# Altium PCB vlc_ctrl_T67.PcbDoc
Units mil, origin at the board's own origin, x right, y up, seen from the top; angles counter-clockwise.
Board outline 1000 x 850 mil, 2 copper layers (Top Layer, Bottom Layer); 16 components, 12 nets, 46 pads, 1 vias.
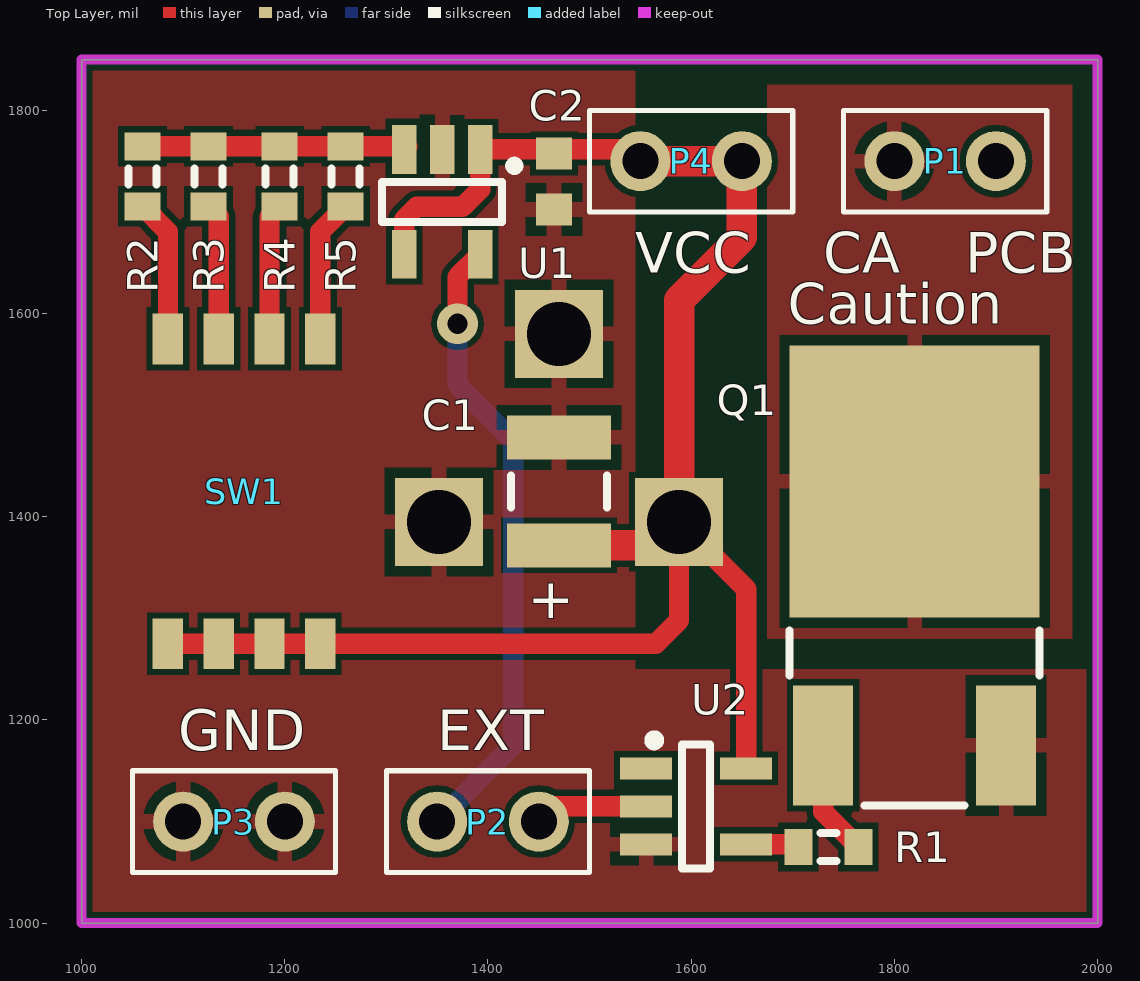
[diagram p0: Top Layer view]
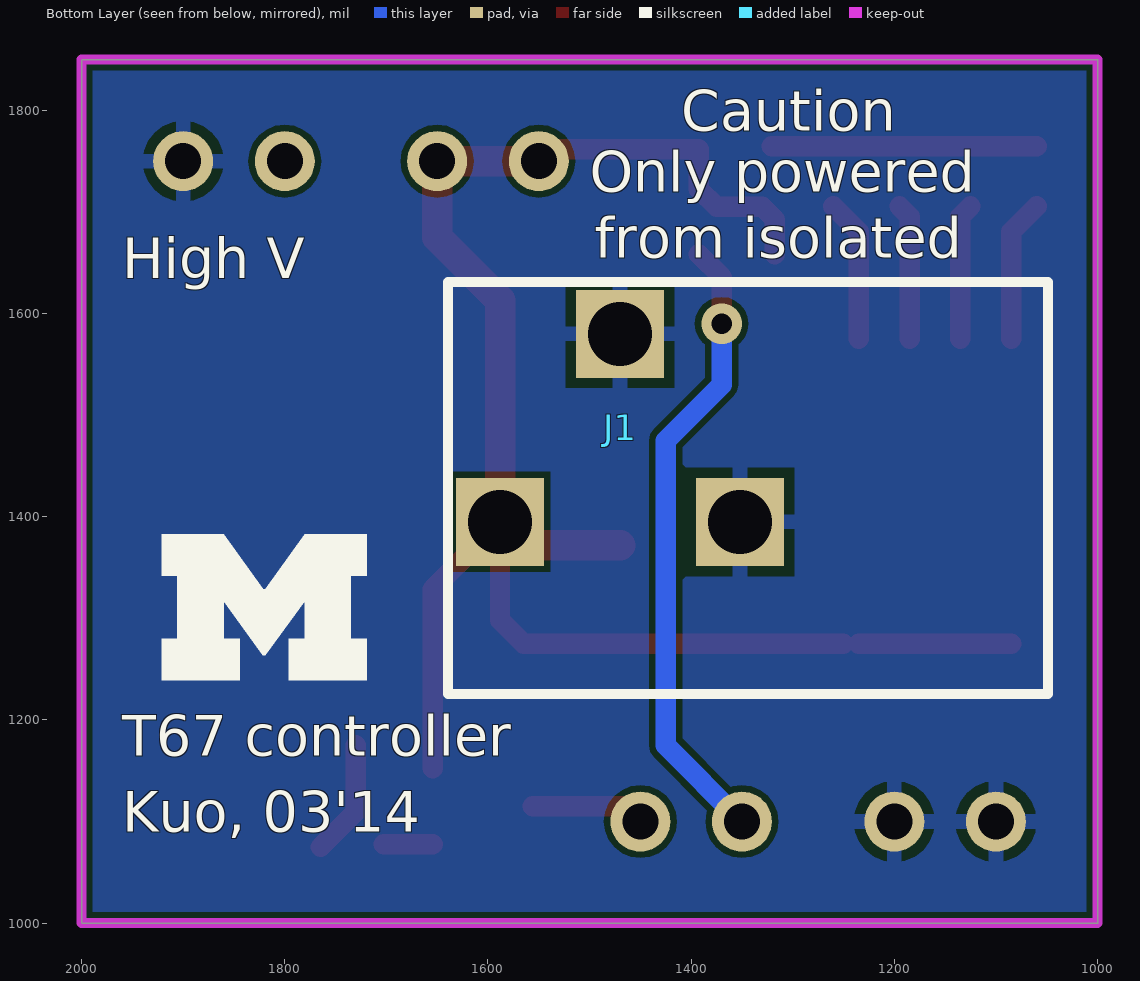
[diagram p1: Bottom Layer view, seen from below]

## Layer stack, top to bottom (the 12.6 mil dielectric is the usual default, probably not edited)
Top Solder: solder mask 0.4, Solder Resist, Dk 3.5
Top Layer: signal copper 1.4
Dielectric 1: dielectric 12.6, FR-4, Dk 4.8
Bottom Layer: signal copper 1.4
Bottom Solder: solder mask 0.4, Solder Resist, Dk 3.5

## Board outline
1000,1000 1000,1850 2000,1850 2000,1000

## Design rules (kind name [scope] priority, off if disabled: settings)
Clearance "Clearance~Sunstone Circuits" [All] p1: gap=6 // Sunstone Circuits Minimum Clearance Rule (Double Sided)
HoleSize "HoleSize~Sunstone Circuits" [All] p1: absolutevalues=TRUE maxlimit=251 minlimit=16 maxpercent=80.000 minpercent=20.000 // SSC Hole Size Rule For Single Sided & Double Sided Designs.
HoleSize Testpoint [All] p2: absolutevalues=TRUE maxlimit=100 minlimit=1 maxpercent=80.000 minpercent=20.000
HoleSize TestPointUsage [All] p3: absolutevalues=TRUE maxlimit=100 minlimit=1 maxpercent=80.000 minpercent=20.000
MinimumAnnularRing "MinimumAnnularRing~Sunstone Circuits" [All] p1: minimumring=7 // Sunstone Circuits Minimum Annular Ring (Double Sided)
PlaneClearance "PlaneClearance~Sunstone Circuits" [All] p1: clearance=12 // Sunstone Circuits Power Plane Clearance Rule (Double Sided)
PlaneConnect "PlaneConnect~Sunstone Circuits" [All] p1: planeconnectstyle=Relief reliefexpansion=10 reliefentries=4 reliefconductorwidth=8 reliefairgap=10 // Sunstone Circuits Power Plane Connect Rule (Double Sided)
PolygonConnect "PolygonConnect~Sunstone Circuits" [All] p1: connectstyle=Relief reliefconductorwidth=15 reliefentries=4 polygonreliefangle="90 Angle" airgapwidth=10 // Sunstone Circuits Polygon Connect Style (Double Sided)
RoomDefinition vlc_ctrl_T67 [InComponentClass('vlc_ctrl_T67')] p1: confinementstyle=ConfineIn formatcopy=TRUE lockcomponents=FALSE outline 1026.38,1675.79 1026.38,1794.21 1282.01,1794.21 1282.01,1798.59 1487.5,1798.59 1487.5,1812.5 1962.5,1812.5 1962.5,1687.5 1959.92,1687.5 1959.92,1102.01 1848.62,1102.01 1848.62,1045.79 1695.71,1045.79 1695.71,1038.07 1512.5,1038.07 1512.5,1037.5 1037.5,1037.5 1037.5,1210.71 1031.35,1210.71 1031.35,1675.79
RoutingVias "RoutingVias~Sunstone Circuits" [All] p1: holewidth=16 width=30 viastyle="Through Hole" minholewidth=16 minwidth=30 maxholewidth=20 maxwidth=40 // Sunstone Circuits Routing Vias Rule (Double Sided)
ShortCircuit "ShortCircuit~Sunstone Circuits" [All] p1: allowed=FALSE // Sunstone Circuits Short Circuit Rule~Do Not Allow (Double Sided)
SolderMaskExpansion "SolderMaskExpansion~Sunstone Circuits" [All] p1: expansion=3 // Sunstone Circuits Solder Mask Expansion Rule (Double Sided)
ViasUnderSMD "ViasUnderSMD~Sunstone Circuits" [All] p1: allowed=FALSE // Sunstone Circuits Vias Under SMD~Do Not Allow (Double Sided)
Width "Width~Sunstone Circuits" [All] p1: maxlimit=100 minlimit=6 preferedwidth=10 // Sunstone Circuits Minimum Width Rule (Double Sided)
25 further rules are at their usual default settings.

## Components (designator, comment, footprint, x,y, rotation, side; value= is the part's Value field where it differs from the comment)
C1 "Cap Semi" C1210 1470,1425 r270 top
C2 "Cap Semi" 1608[0603] 1465,1730 r90 top
J1 "PJ-102AH" PJ-102AH 1470,1395 r270 bottom
P1 "1 x 2 header" "1X2 HEADER" 1850,1750 r0 top
P2 "1 x 2 header" "1X2 HEADER" 1400,1100 r0 top
P3 "1 x 2 header" "1X2 HEADER" 1150,1100 r180 top
P4 "1 x 2 header" "1X2 HEADER" 1600,1750 r180 top
Q1 "AOD3N60" TO252 1820,1175 r0 top
R1 "Res3" J1-0603 1735,1075 r180 top
R2 "Res3" J1-0603 1060,1735 r270 top
R3 "Res3" J1-0603 1125,1735 r270 top
R4 "Res3" J1-0603 1195,1735 r270 top
R5 "Res3" J1-0603 1260,1735 r270 top
SW1 "CHS-04TB" CHS04TB 1160,1425 r0 top
U1 "LTC6900" TSOT23 1355,1710 r180 top
U2 "SN74LVC1G17" SOT23-5 1605,1115 r0 top

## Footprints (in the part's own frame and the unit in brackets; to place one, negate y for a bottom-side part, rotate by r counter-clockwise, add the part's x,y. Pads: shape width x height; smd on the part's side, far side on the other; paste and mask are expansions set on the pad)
"1X2 HEADER" [mm] "1x2 header, 100 mils"
  round 1.5 hole 0.9: 1(-1.27,0) 2(1.27,0)
  silkscreen extent -2.54,-1.27 2.54,1.27, body extent -2.53,-1.26 2.53,1.26, height 8.38
1608[0603] [mm] "Chip Capacitor, Body 1.6x0.8mm, IPC High Density"
  rect 0.8x0.9 smd: 1(-0.7,0) 2(0.7,0)
  body extent -0.87,-0.48 0.87,0.48, height 1.3
C1210 [mm] "Chip Capacitor, Body 3.2x2.5mm, IPC High Density"
  rect 1.1x2.6 smd: 1(-1.35,0) 2(1.35,0)
  silkscreen extent -0.4,-1.2 0.4,1.2, body extent -1.7,-1.35 1.7,1.35, height 1.3
CHS04TB [mm] "4 POS DIP SWITCH"
  rect 0.76x1.27 smd: 1(-1.905,-3.81) 2(-1.905,3.81) 3(-0.635,-3.81) 4(-0.635,3.81) 5(0.635,-3.81) 6(0.635,3.81) 7(1.905,-3.81) 8(1.905,3.81)
J1-0603 [mm] "Chip Resistor, Body 1.6x0.8mm, IPC High Density"
  rect 0.7x0.9 smd: 1(-0.75,0) 2(0.75,0)
  silkscreen extent -0.2,-0.35 0.2,0.35, body extent -0.85,-0.48 0.85,0.48, height 0.9
PJ-102AH [mm] "Power Jack"
  rect 2.2x2.2 hole 1.6: 1(0,-3) 2(0,3) 3(-4.7,0)
  silkscreen extent -6,-4.3 4.3,10.7, body extent -5.75,-3.99 4.08,10.89, height 10
SOT23-5 [mm] "SOT23, 5-Leads, Body 2.9x1.6mm, Pitch 0.95mm, Lead Span 2.8mm, IPC High Density"
  rect 1.3x0.55 smd: 1(-1.25,0.95) 2(-1.25,0) 3(-1.25,-0.95) 4(1.25,-0.95) 5(1.25,0.95)
  silkscreen extent -1.17,-1.55 0.35,1.77, body extent -0.67,-1.5 0.65,1.5, height 1.45
TO252 [mm] "TO252-3"
  rect 1.5x3 smd: 1(-2.286,0) 3(2.286,0)
  rect 6.25x6.8 smd: 4(0,6.6)
  silkscreen extent -3.13,-1.5 3.13,2.88, body extent -3.3,2.98 3.3,9.08, height 2.3
TSOT23 [mm]
  rect 0.62x1.22 smd: 1(-0.95,-1.31) 2(0,-1.31) 3(0.95,-1.31) 4(0.95,1.31) 5(-0.95,1.31)
  silkscreen extent -1.9,-1 1.5,0.5

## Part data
C1 C2: "Capacitor (Semiconductor SIM Model)"
J1: "CONN PWR JACK 2.1X5.5MM HIGH CUR"
P1 P2 P3 P4: "100 mils standard header"
Q1: "600V,2.5A N-Channel MOSFET"
R1 R2 R3 R4 R5: "Resistor"
SW1: "SLIDE SWITCHES"
U1: "Low Power, 1kHz to 20MHz   Resistor Set SOT-23 Oscillator"
U2: "SINGLE SCHMITT-TRIGGER BUFFER"

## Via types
v1: diameter 40, hole 20, Top Layer to Bottom Layer, 1 vias

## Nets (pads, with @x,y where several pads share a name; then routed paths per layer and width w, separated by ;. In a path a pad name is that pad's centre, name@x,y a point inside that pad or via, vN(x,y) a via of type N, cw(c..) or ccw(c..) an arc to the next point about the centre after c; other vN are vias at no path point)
GND: C1.1 C2.1 J1.2 J1.3 P1.2 P3.1 P3.2 Q1.3 U1.2 U2.3
NetP1_1: P1.1 Q1.4
NetP2_1: P2.1 U1.5 | length 621.6
  Top Layer w20: v1(1370,1590) 1370,1636.02 U1.5
  Bottom Layer w20: P2.1 1425,1175 1425,1475 1370,1530 v1(1370,1590)
NetP2_2: P2.2 U2.2 | length 112
  Top Layer w20: P2.2 1465,1115 U2.2
NetQ1_1: Q1.1 R1.1 | length 114.3
  Top Layer w20: Q1.1 1730,1109.53 R1.1
NetR1_2: R1.2 U2.4 | length 48.7
  Top Layer w20: U2.4 R1.2@1702.87,1077.6
NetR2_1: R2.1 R3.1 R4.1 R5.1 U1.3 | length 260.6
  Top Layer w20: R2.1 R3.1 R4.1 R5.1 U1.3@1320.55,1764.53
NetR2_2: R2.2 SW1.2 | length 140.8
  Top Layer w20: R2.2 1085,1680.47 SW1.2
NetR3_2: R3.2 SW1.4 | length 134.6
  Top Layer w20: R3.2 1135,1695.47 SW1.4
NetR4_2: R4.2 SW1.6 | length 134.6
  Top Layer w20: SW1.6 1185,1695.47 R4.2
NetR5_2: R5.2 SW1.8 | length 140.8
  Top Layer w20: SW1.8 1235,1680.47 R5.2
VCC5: C1.2 C2.2 J1.1 P4.1 P4.2 SW1.1 SW1.3 SW1.5 SW1.7 U1.1 U1.4 U2.5 | length 1795.8
  Top Layer w20: SW1.1 SW1.3 SW1.5 SW1.7 ; 1250,1275 1565,1275 1588.11,1298.11 J1.1 1654.21,1328.9 U2.5 ; U1.4 1317.6,1692.6 1330,1705 1375,1705 1392.4,1722.4 U1.1 1538.43,1761.57 P4.2
  Top Layer w30: C1.2 1564.96,1371.85 J1.1 1588.11,1613.11 1650,1675 P4.1 P4.2
pads on no net: U2.1

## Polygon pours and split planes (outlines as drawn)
GND on Bottom Layer "Bottom Layer-No Net" (solid, pour order 8): 1000,1000 2000,1000 2000,1850 1000,1850
GND on Top Layer "Bottom Layer-No Net" (solid, pour order 6): 2000,1250 2000,1000 1000,1000 1000,1850 1545,1850 1545,1250
NetP1_1 on Top Layer "Bottom Layer-No Net" (solid, pour order 2): 1675,1280 1975,1280 1975,1825 1675,1825

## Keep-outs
Keep-Out Layer:
  the board outline again, w10

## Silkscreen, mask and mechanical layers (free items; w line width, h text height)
Top Overlay:
  text "VCC" at 1545,1640 h40
  text "CA" at 1730,1640 h40
  text "PCB" at 1870,1640 h40
  text "Caution" at 1695,1590 h40
  text "+" at 1485,1300 h40
  text "GND" at 1095,1170 h40
  text "EXT" at 1350,1170 h40
Bottom Overlay:
  region: 1920.96,1239.04 1844.23,1239.04 1844.23,1280 1859.84,1280 1859.84,1317.06 1821.8,1263.74 1819.2,1263.74 1780.51,1317.06 1780.51,1280 1796.12,1280 1796.12,1239.04 1719.4,1239.04 1719.4,1280 1735,1280 1735,1341.77 1719.4,1341.77 1719.4,1382.73 1780.19,1382.73 1819.2,1328.76 1821.15,1328.76 1860.16,1382.73 1920.96,1382.73 1920.96,1341.77 1906,1341.77 1906,1280 1920.96,1280
  text "Caution" at 1410,1780 h40
  text "Only powered" at 1500,1720 h40
  text "from isolated" at 1495,1655 h40
  text "High V" at 1960,1635 h40
  text "T67 controller" at 1960,1165 h40
  text "Kuo, 03'14" at 1960,1090 h40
